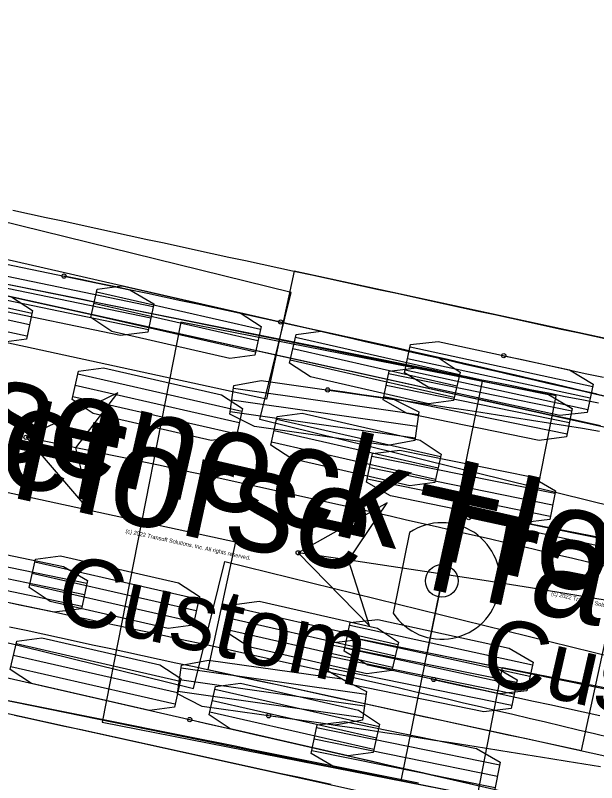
# Model space of a CAD drawing. Extents: x -14 to 1565148, y -25 to 642856.
# Drawn here: x 1564670.24 to 1564681.64, y 636312.5 to 636327.56 of the extents above; entities that cross this region are included whole.
import ezdxf

# ---------------------------------------------------------------- set-up
doc = ezdxf.new("R2010")
doc.units = 0
for name, color, linetype in [('CM_Corridor_Conceptual', 7, 'Continuous'), ('CM_Corridor_Key_Station', 7, 'Continuous'), ('PV_P_Saw_Cut_Line', 7, 'Continuous'), ('TR_Turning_Path22', 7, 'Continuous'), ('TR_Turning_Path23', 7, 'Continuous'), ('TR_Turning_Path24', 7, 'Continuous')]:
    doc.layers.add(name, color=color, linetype=linetype)

msp = doc.modelspace()

# ---------------------------------------------------------------- linework, layer by layer
at = {"layer": 'CM_Corridor_Conceptual'}
for p, q in [((1564675.649, 636322.118), (1564668.367, 636323.912)), ((1564669.352, 636322.59), (1564672.942, 636321.846)), ((1564669.305, 636322.366), (1564672.896, 636321.621)), ((1564669.259, 636322.141), (1564672.849, 636321.397)), ((1564675.035, 636319.626), (1564675.649, 636322.118)), ((1564684.745, 636317.234), (1564675.035, 636319.626)), ((1564668.05, 636317.16), (1564671.64, 636316.418)), ((1564668.003, 636316.936), (1564671.594, 636316.193)), ((1564673.736, 636314.35), (1564674.35, 636316.842)), ((1564674.35, 636316.842), (1564684.06, 636314.451)), ((1564667.957, 636316.712), (1564671.548, 636315.969)), ((1564666.454, 636316.144), (1564673.736, 636314.35))]:
    msp.add_line(p, q, dxfattribs=at)
for points in [[(1564669.247, 636322.086), (1564669.363, 636322.646), (1564669.901, 636322.71), (1564672.486, 636322.174), (1564672.954, 636321.901), (1564672.838, 636321.341), (1564672.3, 636321.277), (1564669.715, 636321.813)], [(1564670.45, 636319.279), (1564671.756, 636317.765), (1564671.429, 636319.076), (1564672.251, 636320.149)], [(1564667.945, 636316.656), (1564668.061, 636317.216), (1564668.599, 636317.281), (1564671.184, 636316.746), (1564671.652, 636316.473), (1564671.536, 636315.913), (1564670.998, 636315.848), (1564668.413, 636316.383)]]:
    msp.add_lwpolyline(points, close=True, dxfattribs=at)
for points in [[(1564681.655, 636320.124), (1564681.329, 636320.201), (1564681.003, 636320.277), (1564680.677, 636320.353), (1564680.351, 636320.429), (1564680.025, 636320.505), (1564679.698, 636320.58), (1564679.372, 636320.656), (1564679.046, 636320.73), (1564678.719, 636320.805), (1564678.393, 636320.879), (1564678.066, 636320.953), (1564677.739, 636321.027), (1564677.413, 636321.1), (1564677.086, 636321.173), (1564676.759, 636321.246), (1564676.432, 636321.319), (1564676.105, 636321.391), (1564675.778, 636321.463), (1564675.451, 636321.535), (1564675.124, 636321.606), (1564674.797, 636321.678), (1564674.47, 636321.749), (1564674.142, 636321.819), (1564673.815, 636321.89), (1564673.487, 636321.96), (1564673.16, 636322.029), (1564672.832, 636322.099), (1564672.505, 636322.168), (1564672.177, 636322.237), (1564671.849, 636322.306), (1564671.521, 636322.374), (1564671.194, 636322.442)], [(1564670.45, 636319.279), (1564671.756, 636317.765), (1564671.429, 636319.076), (1564672.251, 636320.149), (1564670.45, 636319.279)], [(1564681.918, 636313.382), (1564681.597, 636313.459), (1564681.277, 636313.536), (1564680.957, 636313.613), (1564680.636, 636313.689), (1564680.316, 636313.765), (1564679.995, 636313.84), (1564679.675, 636313.916), (1564679.354, 636313.991), (1564679.033, 636314.066), (1564678.713, 636314.14), (1564678.392, 636314.214), (1564678.071, 636314.288), (1564677.75, 636314.362), (1564677.429, 636314.436), (1564677.108, 636314.509), (1564676.787, 636314.582), (1564676.465, 636314.654), (1564676.144, 636314.727), (1564675.823, 636314.799), (1564675.501, 636314.871), (1564675.18, 636314.942), (1564674.858, 636315.013), (1564674.537, 636315.084), (1564674.215, 636315.155), (1564673.893, 636315.225), (1564673.572, 636315.296), (1564673.25, 636315.365), (1564672.928, 636315.435), (1564672.606, 636315.504), (1564672.284, 636315.573), (1564671.962, 636315.642), (1564671.64, 636315.711), (1564671.318, 636315.779), (1564670.995, 636315.847), (1564670.673, 636315.914), (1564670.351, 636315.982), (1564670.028, 636316.049)]]:
    msp.add_lwpolyline(points, dxfattribs=at)
for centre in [(1564671.194, 636322.442), (1564670.45, 636319.279)]:
    msp.add_circle(centre, 0.0417, dxfattribs=at)
msp.add_arc((1564591.587, 635938.467), 388.892, 75.16867, 78.30003, dxfattribs=at)
at = {"layer": 'CM_Corridor_Key_Station'}
for p, q in [((1564692.443, 636317.134), (1564657.283, 636324.867)), ((1564670.565, 636321.711), (1564667.342, 636322.42)), ((1564670.516, 636321.487), (1564667.293, 636322.196)), ((1564670.467, 636321.263), (1564667.244, 636321.972)), ((1564655.565, 636317.054), (1564690.724, 636309.321))]:
    msp.add_line(p, q, dxfattribs=at)
msp.add_lwpolyline([(1564670.577, 636321.767), (1564670.455, 636321.208), (1564669.966, 636321.139), (1564667.646, 636321.649), (1564667.232, 636321.917), (1564667.354, 636322.475), (1564667.843, 636322.545), (1564670.163, 636322.034)], close=True, dxfattribs=at)
for points in [[(1564669.985, 636322.074), (1564670.311, 636322.002), (1564670.637, 636321.93), (1564670.963, 636321.859), (1564671.289, 636321.787), (1564671.615, 636321.716), (1564671.941, 636321.644), (1564672.267, 636321.572), (1564672.593, 636321.501), (1564672.919, 636321.429), (1564673.245, 636321.358), (1564673.571, 636321.287), (1564673.897, 636321.215), (1564674.223, 636321.144), (1564674.549, 636321.072), (1564674.875, 636321.001), (1564675.201, 636320.93), (1564675.527, 636320.858), (1564675.853, 636320.787), (1564676.179, 636320.716), (1564676.505, 636320.645), (1564676.831, 636320.574), (1564677.157, 636320.502), (1564677.483, 636320.431), (1564677.809, 636320.36), (1564678.134, 636320.289), (1564678.46, 636320.218), (1564678.786, 636320.147), (1564679.112, 636320.076), (1564679.438, 636320.006), (1564679.764, 636319.935), (1564680.09, 636319.864), (1564680.416, 636319.793), (1564680.742, 636319.723), (1564681.068, 636319.652), (1564681.394, 636319.581), (1564681.72, 636319.511)], [(1564670.226, 636313.83), (1564670.553, 636313.758), (1564670.879, 636313.687), (1564671.205, 636313.615), (1564671.532, 636313.544), (1564671.859, 636313.472), (1564672.185, 636313.4), (1564672.512, 636313.329), (1564672.838, 636313.257), (1564673.165, 636313.186), (1564673.491, 636313.115), (1564673.818, 636313.043), (1564674.145, 636312.972), (1564674.471, 636312.9), (1564674.798, 636312.829), (1564675.125, 636312.758), (1564675.451, 636312.686), (1564675.778, 636312.615), (1564676.105, 636312.544), (1564676.431, 636312.473)]]:
    msp.add_lwpolyline(points, dxfattribs=at)
at = {"layer": 'PV_P_Saw_Cut_Line'}
for p, q in [((1564700.79, 636315.751), (1564665.694, 636323.767)), ((1564675.05, 636321.395), (1564671.833, 636322.13)), ((1564674.999, 636321.172), (1564671.782, 636321.907)), ((1564674.948, 636320.948), (1564671.731, 636321.683)), ((1564678.95, 636320.504), (1564675.733, 636321.239)), ((1564678.899, 636320.281), (1564675.682, 636321.016)), ((1564678.848, 636320.058), (1564675.631, 636320.792)), ((1564674.683, 636319.787), (1564671.466, 636320.521)), ((1564674.632, 636319.563), (1564671.415, 636320.298)), ((1564674.581, 636319.34), (1564671.364, 636320.075)), ((1564678.582, 636318.896), (1564675.365, 636319.631)), ((1564678.531, 636318.672), (1564675.314, 636319.407)), ((1564678.48, 636318.449), (1564675.263, 636319.184)), ((1564673.84, 636316.098), (1564670.623, 636316.833)), ((1564673.789, 636315.875), (1564670.572, 636316.61)), ((1564673.738, 636315.651), (1564670.521, 636316.386)), ((1564663.912, 636315.968), (1564699.008, 636307.952)), ((1564677.74, 636315.208), (1564674.523, 636315.942)), ((1564677.689, 636314.984), (1564674.472, 636315.719)), ((1564677.638, 636314.761), (1564674.421, 636315.496)), ((1564673.473, 636314.49), (1564670.256, 636315.225)), ((1564673.422, 636314.266), (1564670.205, 636315.001)), ((1564673.371, 636314.043), (1564670.154, 636314.778)), ((1564677.373, 636313.599), (1564674.155, 636314.334)), ((1564677.322, 636313.376), (1564674.104, 636314.11)), ((1564677.27, 636313.152), (1564674.053, 636313.887))]:
    msp.add_line(p, q, dxfattribs=at)
for points in [[(1564675.063, 636321.451), (1564674.936, 636320.893), (1564674.447, 636320.828), (1564672.13, 636321.357), (1564671.718, 636321.628), (1564671.846, 636322.185), (1564672.335, 636322.251), (1564674.651, 636321.721)], [(1564678.963, 636320.56), (1564678.835, 636320.002), (1564678.346, 636319.937), (1564676.03, 636320.466), (1564675.618, 636320.737), (1564675.745, 636321.295), (1564676.234, 636321.36), (1564678.551, 636320.831)], [(1564674.696, 636319.842), (1564674.568, 636319.284), (1564674.079, 636319.219), (1564671.763, 636319.748), (1564671.351, 636320.019), (1564671.478, 636320.577), (1564671.967, 636320.642), (1564674.284, 636320.113)], [(1564678.595, 636318.951), (1564678.468, 636318.394), (1564677.979, 636318.329), (1564675.663, 636318.858), (1564675.251, 636319.128), (1564675.378, 636319.686), (1564675.867, 636319.751), (1564678.183, 636319.222)], [(1564673.853, 636316.154), (1564673.726, 636315.596), (1564673.237, 636315.531), (1564670.921, 636316.06), (1564670.509, 636316.331), (1564670.636, 636316.889), (1564671.125, 636316.954), (1564673.441, 636316.425)], [(1564677.753, 636315.263), (1564677.625, 636314.705), (1564677.136, 636314.64), (1564674.82, 636315.169), (1564674.408, 636315.44), (1564674.535, 636315.998), (1564675.024, 636316.063), (1564677.341, 636315.534)], [(1564673.486, 636314.545), (1564673.358, 636313.987), (1564672.869, 636313.922), (1564670.553, 636314.451), (1564670.141, 636314.722), (1564670.269, 636315.28), (1564670.757, 636315.345), (1564673.074, 636314.816)], [(1564677.385, 636313.654), (1564677.258, 636313.097), (1564676.769, 636313.032), (1564674.453, 636313.561), (1564674.041, 636313.832), (1564674.168, 636314.389), (1564674.657, 636314.454), (1564676.973, 636313.925)]]:
    msp.add_lwpolyline(points, close=True, dxfattribs=at)
for points in [[(1564675.443, 636321.541), (1564675.768, 636321.466), (1564676.094, 636321.392), (1564676.42, 636321.317), (1564676.746, 636321.243), (1564677.072, 636321.168), (1564677.398, 636321.094), (1564677.724, 636321.02), (1564678.049, 636320.945), (1564678.375, 636320.871), (1564678.701, 636320.797), (1564679.027, 636320.722), (1564679.353, 636320.648), (1564679.678, 636320.574), (1564680.004, 636320.5), (1564680.33, 636320.425), (1564680.655, 636320.351), (1564680.981, 636320.277), (1564681.307, 636320.203), (1564681.633, 636320.129), (1564681.958, 636320.055)], [(1564673.661, 636313.742), (1564673.987, 636313.667), (1564674.313, 636313.593), (1564674.639, 636313.518), (1564674.965, 636313.444), (1564675.291, 636313.369), (1564675.617, 636313.295), (1564675.943, 636313.22), (1564676.269, 636313.146), (1564676.596, 636313.072), (1564676.922, 636312.997), (1564677.248, 636312.923), (1564677.574, 636312.848), (1564677.9, 636312.774), (1564678.226, 636312.7), (1564678.553, 636312.625), (1564678.879, 636312.551), (1564679.205, 636312.477)]]:
    msp.add_lwpolyline(points, dxfattribs=at)
for centre in [(1564675.443, 636321.541), (1564673.661, 636313.742)]:
    msp.add_circle(centre, 0.0417, dxfattribs=at)
at = {"layer": 'TR_Turning_Path22'}
for p, q in [((1564673.487, 636321.541), (1564671.944, 636313.691)), ((1564680.846, 636320.095), (1564673.487, 636321.541)), ((1564674.519, 636320.242), (1564678.149, 636319.724)), ((1564674.487, 636320.015), (1564678.116, 636319.497)), ((1564680.351, 636317.577), (1564680.846, 636320.095)), ((1564674.454, 636319.788), (1564678.084, 636319.27)), ((1564690.164, 636315.648), (1564680.351, 636317.577)), ((1564673.49, 636314.754), (1564677.12, 636314.239)), ((1564679.303, 636312.245), (1564679.798, 636314.764)), ((1564679.798, 636314.764), (1564689.611, 636312.835)), ((1564673.457, 636314.527), (1564677.088, 636314.012)), ((1564673.425, 636314.3), (1564677.055, 636313.785)), ((1564671.944, 636313.691), (1564679.303, 636312.245)), ((1564671.944, 636313.691), (1564671.944, 636313.691))]:
    msp.add_line(p, q, dxfattribs=at)
for points in [[(1564674.446, 636319.732), (1564674.527, 636320.298), (1564675.06, 636320.396), (1564677.673, 636320.023), (1564678.157, 636319.78), (1564678.076, 636319.214), (1564677.543, 636319.116), (1564674.93, 636319.489)], [(1564675.787, 636317.013), (1564677.185, 636315.583), (1564676.777, 636316.871), (1564677.53, 636317.994)], [(1564673.417, 636314.244), (1564673.498, 636314.81), (1564674.03, 636314.909), (1564676.644, 636314.538), (1564677.128, 636314.295), (1564677.047, 636313.729), (1564676.515, 636313.63), (1564673.901, 636314.001)]]:
    msp.add_lwpolyline(points, close=True, dxfattribs=at)
for points in [[(1564681.697, 636319.396), (1564681.364, 636319.45), (1564681.031, 636319.503), (1564680.698, 636319.556), (1564680.366, 636319.609), (1564680.033, 636319.661), (1564679.7, 636319.713), (1564679.367, 636319.765), (1564679.033, 636319.816), (1564678.7, 636319.866), (1564678.367, 636319.917), (1564678.034, 636319.967), (1564677.7, 636320.016), (1564677.367, 636320.065), (1564677.033, 636320.114), (1564676.7, 636320.162), (1564676.366, 636320.21)], [(1564675.787, 636317.013), (1564677.185, 636315.583), (1564676.777, 636316.871), (1564677.53, 636317.994), (1564675.787, 636317.013)], [(1564681.715, 636312.812), (1564681.39, 636312.866), (1564681.065, 636312.92), (1564680.74, 636312.973), (1564680.415, 636313.025), (1564680.09, 636313.078), (1564679.765, 636313.13), (1564679.44, 636313.181), (1564679.115, 636313.232), (1564678.79, 636313.283), (1564678.464, 636313.334), (1564678.139, 636313.384), (1564677.814, 636313.433), (1564677.488, 636313.482), (1564677.163, 636313.531), (1564676.837, 636313.58), (1564676.511, 636313.628), (1564676.186, 636313.675), (1564675.86, 636313.722), (1564675.534, 636313.769), (1564675.208, 636313.816)]]:
    msp.add_lwpolyline(points, dxfattribs=at)
for centre in [(1564676.366, 636320.21), (1564675.787, 636317.013), (1564675.208, 636313.816)]:
    msp.add_circle(centre, 0.0417, dxfattribs=at)
msp.add_arc((1564636.885, 636043.718), 276.049, 69.66154, 81.89867, dxfattribs=at)
at = {"layer": 'TR_Turning_Path23'}
for p, q in [((1564675.709, 636322.54), (1564675.166, 636320.031)), ((1564683.039, 636320.951), (1564675.709, 636322.54)), ((1564675.166, 636320.031), (1564665.393, 636322.149)), ((1564681.564, 636320.268), (1564677.981, 636321.045)), ((1564681.344, 636313.132), (1564683.039, 636320.951)), ((1564681.516, 636320.045), (1564677.932, 636320.821)), ((1564681.467, 636319.821), (1564677.884, 636320.597)), ((1564664.785, 636319.348), (1564674.558, 636317.229)), ((1564679.133, 636317.705), (1564730.638, 636306.541)), ((1564674.558, 636317.229), (1564674.015, 636314.721)), ((1564680.382, 636314.812), (1564676.798, 636315.589)), ((1564680.333, 636314.588), (1564676.75, 636315.365)), ((1564680.285, 636314.364), (1564676.701, 636315.141)), ((1564674.015, 636314.721), (1564681.344, 636313.132))]:
    msp.add_line(p, q, dxfattribs=at)
for points in [[(1564670.191, 636323.736), (1564670.517, 636323.665), (1564670.843, 636323.594), (1564671.169, 636323.524), (1564671.494, 636323.453), (1564671.82, 636323.382), (1564672.146, 636323.312), (1564672.472, 636323.241), (1564672.798, 636323.17), (1564673.124, 636323.1), (1564673.45, 636323.029), (1564673.776, 636322.958), (1564674.102, 636322.888), (1564674.428, 636322.817), (1564674.754, 636322.747), (1564675.08, 636322.676), (1564675.406, 636322.605), (1564675.732, 636322.535), (1564676.058, 636322.464), (1564676.384, 636322.393), (1564676.71, 636322.323), (1564677.036, 636322.252), (1564677.362, 636322.181), (1564677.688, 636322.111), (1564678.014, 636322.04), (1564678.34, 636321.969), (1564678.666, 636321.899), (1564678.992, 636321.828), (1564679.318, 636321.757), (1564679.644, 636321.687), (1564679.97, 636321.616), (1564680.296, 636321.545), (1564680.622, 636321.475), (1564680.948, 636321.404), (1564681.274, 636321.333), (1564681.6, 636321.263), (1564681.926, 636321.192)], [(1564679.821, 636320.881), (1564680.147, 636320.81), (1564680.473, 636320.739), (1564680.799, 636320.669), (1564681.125, 636320.598), (1564681.451, 636320.528), (1564681.777, 636320.457)], [(1564670.126, 636315.564), (1564670.452, 636315.493), (1564670.778, 636315.423), (1564671.104, 636315.352), (1564671.43, 636315.281), (1564671.756, 636315.211), (1564672.082, 636315.14), (1564672.408, 636315.069), (1564672.734, 636314.999), (1564673.06, 636314.928), (1564673.386, 636314.857), (1564673.712, 636314.787), (1564674.038, 636314.716), (1564674.364, 636314.645), (1564674.689, 636314.575), (1564675.015, 636314.504), (1564675.341, 636314.433), (1564675.667, 636314.363), (1564675.993, 636314.292), (1564676.319, 636314.222), (1564676.645, 636314.151), (1564676.971, 636314.08), (1564677.297, 636314.01), (1564677.623, 636313.939), (1564677.949, 636313.868), (1564678.275, 636313.798), (1564678.601, 636313.727), (1564678.927, 636313.656), (1564679.253, 636313.586), (1564679.579, 636313.515), (1564679.905, 636313.444), (1564680.231, 636313.374), (1564680.557, 636313.303), (1564680.883, 636313.232), (1564681.209, 636313.162), (1564681.535, 636313.091), (1564681.861, 636313.02)], [(1564678.444, 636314.528), (1564678.77, 636314.458), (1564679.096, 636314.387), (1564679.422, 636314.316), (1564679.748, 636314.246), (1564680.074, 636314.175), (1564680.4, 636314.104), (1564680.726, 636314.034), (1564681.052, 636313.963), (1564681.378, 636313.892), (1564681.704, 636313.822)]]:
    msp.add_lwpolyline(points, dxfattribs=at)
for points in [[(1564681.576, 636320.324), (1564681.455, 636319.765), (1564680.917, 636319.705), (1564678.337, 636320.265), (1564677.872, 636320.542), (1564677.993, 636321.101), (1564678.531, 636321.16), (1564681.111, 636320.601)], [(1564680.394, 636314.867), (1564680.273, 636314.308), (1564679.734, 636314.249), (1564677.154, 636314.808), (1564676.689, 636315.085), (1564676.81, 636315.644), (1564677.348, 636315.704), (1564679.929, 636315.145)]]:
    msp.add_lwpolyline(points, close=True, dxfattribs=at)
for centre in [(1564679.821, 636320.881), (1564679.133, 636317.705), (1564678.444, 636314.528)]:
    msp.add_circle(centre, 0.0417, dxfattribs=at)
at = {"layer": 'TR_Turning_Path24'}
for p, q in [((1564679.402, 636320.381), (1564644.125, 636327.558)), ((1564681.153, 636319.79), (1564677.56, 636320.522)), ((1564677.807, 636312.541), (1564679.402, 636320.381)), ((1564679.402, 636320.381), (1564679.402, 636320.381)), ((1564681.107, 636319.566), (1564677.514, 636320.297)), ((1564681.061, 636319.341), (1564677.468, 636320.072)), ((1564642.529, 636319.719), (1564677.807, 636312.541)), ((1564680.824, 636318.174), (1564677.231, 636318.905)), ((1564680.778, 636317.949), (1564677.185, 636318.68)), ((1564680.732, 636317.724), (1564677.139, 636318.456)), ((1564678.89, 636317.865), (1564678.318, 636315.056)), ((1564688.689, 636315.872), (1564678.89, 636317.865)), ((1564677.973, 636317.414), (1564677.651, 636315.83)), ((1564680.069, 636314.466), (1564676.476, 636315.197)), ((1564678.318, 636315.056), (1564688.118, 636313.063)), ((1564680.024, 636314.242), (1564676.431, 636314.973)), ((1564679.978, 636314.017), (1564676.385, 636314.748)), ((1564679.74, 636312.849), (1564676.147, 636313.58)), ((1564679.695, 636312.625), (1564676.102, 636313.356)), ((1564679.649, 636312.4), (1564676.056, 636313.131))]:
    msp.add_line(p, q, dxfattribs=at)
for points in [[(1564669.922, 636322.317), (1564670.249, 636322.251), (1564670.575, 636322.185), (1564670.902, 636322.119), (1564671.228, 636322.053), (1564671.555, 636321.987), (1564671.881, 636321.921), (1564672.208, 636321.855), (1564672.534, 636321.789), (1564672.861, 636321.723), (1564673.187, 636321.658), (1564673.514, 636321.592), (1564673.84, 636321.526), (1564674.167, 636321.46), (1564674.493, 636321.394), (1564674.82, 636321.329), (1564675.146, 636321.263), (1564675.473, 636321.197), (1564675.799, 636321.132), (1564676.126, 636321.066), (1564676.452, 636321), (1564676.779, 636320.935), (1564677.105, 636320.869), (1564677.432, 636320.803), (1564677.758, 636320.738), (1564678.085, 636320.672), (1564678.411, 636320.607), (1564678.738, 636320.541), (1564679.064, 636320.476), (1564679.391, 636320.41), (1564679.717, 636320.345), (1564680.044, 636320.28), (1564680.37, 636320.214), (1564680.697, 636320.149), (1564681.023, 636320.083), (1564681.35, 636320.018), (1564681.676, 636319.953)], [(1564669.971, 636314.145), (1564670.298, 636314.079), (1564670.625, 636314.013), (1564670.952, 636313.947), (1564671.279, 636313.881), (1564671.606, 636313.815), (1564671.933, 636313.75), (1564672.26, 636313.684), (1564672.587, 636313.618), (1564672.913, 636313.552), (1564673.24, 636313.486), (1564673.567, 636313.42), (1564673.894, 636313.354), (1564674.221, 636313.289), (1564674.548, 636313.223), (1564674.875, 636313.157), (1564675.202, 636313.092), (1564675.529, 636313.026), (1564675.856, 636312.96), (1564676.183, 636312.894), (1564676.51, 636312.829), (1564676.837, 636312.763), (1564677.164, 636312.698), (1564677.491, 636312.632), (1564677.818, 636312.566), (1564678.145, 636312.501)]]:
    msp.add_lwpolyline(points, dxfattribs=at)
for points in [[(1564681.164, 636319.846), (1564681.05, 636319.286), (1564680.512, 636319.219), (1564677.925, 636319.746), (1564677.457, 636320.017), (1564677.571, 636320.577), (1564678.108, 636320.644), (1564680.695, 636320.117)], [(1564680.835, 636318.229), (1564680.721, 636317.669), (1564680.183, 636317.602), (1564677.596, 636318.129), (1564677.128, 636318.4), (1564677.242, 636318.96), (1564677.779, 636319.027), (1564680.366, 636318.501)], [(1564680.081, 636314.522), (1564679.967, 636313.961), (1564679.429, 636313.895), (1564676.842, 636314.421), (1564676.373, 636314.692), (1564676.488, 636315.253), (1564677.025, 636315.32), (1564679.612, 636314.793)], [(1564679.752, 636312.905), (1564679.638, 636312.345), (1564679.1, 636312.278), (1564676.513, 636312.804), (1564676.045, 636313.076), (1564676.159, 636313.636), (1564676.696, 636313.703), (1564679.283, 636313.176)]]:
    msp.add_lwpolyline(points, close=True, dxfattribs=at)
msp.add_circle((1564678.604, 636316.461), 0.32, dxfattribs=at)
msp.add_arc((1564678.604, 636316.461), 1.143, 213.4992, 123.4992, dxfattribs=at)

# ---------------------------------------------------------------- texts
at = {"layer": 'CM_Corridor_Key_Station'}
for s, height, p in [('Gooseneck Horse Trailer', 2, (1564656.133, 636321.188)), ('(c) 2022 Transoft Solutions, Inc. All rights reserved.', 0.08, (1564672.395, 636317.407)), ('Custom', 1.3333, (1564670.968, 636315.707))]:
    msp.add_text(s, height=height, rotation=347.5961, dxfattribs=at).set_placement(p)
at = {"layer": 'PV_P_Saw_Cut_Line'}
for s, height, p in [('Gooseneck Horse Trailer', 2, (1564664.514, 636320.098)), ('(c) 2022 Transoft Solutions, Inc. All rights reserved.', 0.08, (1564680.745, 636316.185)), ('Custom', 1.3333, (1564679.304, 636314.497))]:
    msp.add_text(s, height=height, rotation=347.1335, dxfattribs=at).set_placement(p)
at = {"layer": 'TR_Turning_Path24'}
msp.add_text('Gooseneck Horse Trailer', height=2, rotation=348.4992, dxfattribs=at).set_placement((1564643.032, 636323.862))

doc.saveas('drawing.dxf')
